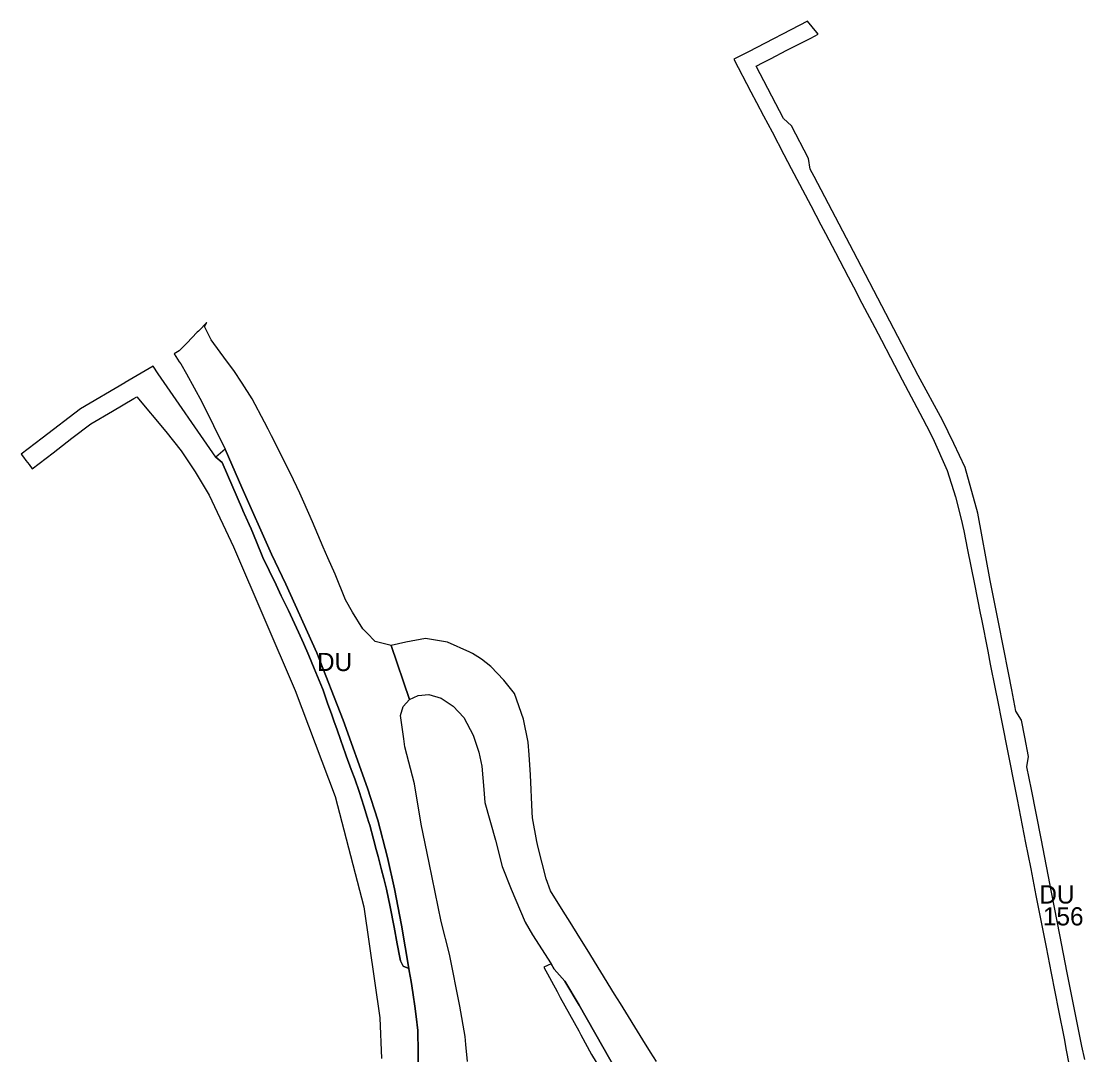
# Model space of a CAD drawing. Extents: x -521047 to -518054, y -1194945 to -1189555.
# Drawn here: x -520976 to -520392, y -1190123 to -1189555 of the extents above; entities that cross this region are included whole.
import ezdxf

# ---------------------------------------------------------------- set-up
doc = ezdxf.new("R2010")
doc.units = 0
for name, color, linetype in [('90310013', 7, 'Continuous'), ('90310023', 7, 'Continuous'), ('90320013', 7, 'Continuous'), ('ID_navrh', 7, 'Continuous')]:
    doc.layers.add(name, color=color, linetype=linetype)

msp = doc.modelspace()

# ---------------------------------------------------------------- linework, layer by layer
at = {"layer": '90310013'}
for points in [[(-520868.84, -1189794.27), (-520865.38, -1189797.27), (-520854.32, -1189823.02), (-520854.03, -1189823.64), (-520852.36, -1189827.29), (-520852.17, -1189827.72), (-520850.55, -1189831.25), (-520849.51, -1189833.76), (-520846.54, -1189840.93), (-520843.01, -1189849.46), (-520839.61, -1189856.58), (-520835.85, -1189864.43), (-520832.97, -1189870.44), (-520829.04, -1189878.62), (-520825.65, -1189885.69), (-520823.49, -1189890.54), (-520820.8, -1189896.58), (-520817.79, -1189903.36), (-520814.9, -1189910.36), (-520810.37, -1189921.35), (-520810.03, -1189922.31), (-520807.51, -1189929.41), (-520805.23, -1189935.82), (-520803.82, -1189939.77), (-520802.52, -1189943.48), (-520800.24, -1189949.98), (-520797.68, -1189957.29), (-520797.3, -1189958.38), (-520794.56, -1189965.83), (-520792.63, -1189971.08), (-520790.16, -1189978), (-520787.64, -1189985.97), (-520785.69, -1189992.16), (-520784.78, -1189995.03), (-520784.38, -1189996.52), (-520782.34, -1190004.2), (-520780.76, -1190009.83), (-520779.7, -1190013.73), (-520778.96, -1190016.65), (-520777.88, -1190020.97), (-520776.66, -1190025.8), (-520775.2, -1190031.58), (-520773.22, -1190041.38), (-520770.98, -1190052.51), (-520769.27, -1190061.72), (-520767.88, -1190069.17), (-520767.55, -1190070.93), (-520766.02, -1190074.02), (-520762.83, -1190075.3), (-520766.84, -1190051.34), (-520770.67, -1190031.38), (-520774.58, -1190014.33), (-520779.86, -1189993.71), (-520785.63, -1189976.16), (-520799.04, -1189938.79), (-520813.42, -1189901.77), (-520830.43, -1189864.05), (-520838.34, -1189847.6), (-520854.68, -1189811.01), (-520863.78, -1189789.93), (-520868.84, -1189794.27)], [(-520630.98, -1190162.68), (-520656.35, -1190118.25), (-520669.33, -1190095.42), (-520677.11, -1190082.08), (-520683.08, -1190075.53), (-520684.77, -1190072.63), (-520688.71, -1190074.44), (-520681.36, -1190087.92), (-520679.67, -1190091.18), (-520669.52, -1190109.47), (-520668.3, -1190111.67), (-520662.54, -1190122.49), (-520650.61, -1190142)]]:
    msp.add_lwpolyline(points, dxfattribs=at)
at = {"layer": '90310023'}
for points in [[(-520538.07, -1189562.04), (-520538.7, -1189561.06), (-520543.9, -1189554.92), (-520576.33, -1189571.62), (-520584.33, -1189575.74), (-520574.91, -1189593.69), (-520571.87, -1189599.49), (-520567.98, -1189606.88), (-520563.29, -1189615.69), (-520556.78, -1189628.12), (-520554.77, -1189631.94), (-520552.78, -1189635.77), (-520542.06, -1189656.2), (-520536.5, -1189666.75), (-520533.97, -1189671.56), (-520528.55, -1189681.89), (-520521.58, -1189695.28), (-520518.55, -1189700.78), (-520513.98, -1189709.68), (-520506.96, -1189723.04), (-520503.29, -1189730.03), (-520498.25, -1189739.55), (-520491.89, -1189751.79), (-520480.47, -1189773.36), (-520478.5, -1189777.12), (-520474.96, -1189783.97), (-520467.22, -1189801.74), (-520462.52, -1189816.05), (-520459.4, -1189828.36), (-520457.93, -1189834.89), (-520455.88, -1189845.31), (-520452.13, -1189864.14), (-520448.96, -1189880.06), (-520448.32, -1189883.37), (-520444.85, -1189900.94), (-520443.47, -1189908.13), (-520440.81, -1189921.53), (-520439.37, -1189928.74), (-520437.33, -1189939.01), (-520429.98, -1189976.03), (-520428.73, -1189982.35), (-520424.06, -1190006.15), (-520422.85, -1190012.32), (-520421.24, -1190020.5), (-520418.36, -1190035.16), (-520413.93, -1190058), (-520412.81, -1190063.42), (-520409.99, -1190077.75), (-520405.98, -1190098.21), (-520402.94, -1190113.68), (-520401.68, -1190120.11), (-520400.22, -1190127.57)], [(-520391.56, -1190125.16), (-520393.2, -1190117.89), (-520397.27, -1190097.65), (-520401.22, -1190077.65), (-520405.21, -1190056.77), (-520409.61, -1190034.24), (-520415.58, -1190003.82), (-520420.88, -1189976.82), (-520423.3, -1189964.53), (-520422.41, -1189958.68), (-520424.49, -1189948.09), (-520426.3, -1189938.88), (-520429.34, -1189933.8), (-520431.66, -1189922.07), (-520433.46, -1189912.89), (-520438.94, -1189885.01), (-520443.42, -1189862.15), (-520450.25, -1189825.06), (-520457.28, -1189799.95), (-520463.47, -1189786.79), (-520469.68, -1189773.95), (-520483.13, -1189749.49), (-520518.67, -1189681.41), (-520540.29, -1189640.25), (-520542.46, -1189636.12), (-520543.28, -1189630.26), (-520552.66, -1189612.4), (-520557.02, -1189608.4), (-520572.14, -1189579.59), (-520568.14, -1189577.53), (-520564.14, -1189575.47), (-520555.14, -1189570.83), (-520546.14, -1189566.2), (-520542.1, -1189564.12), (-520538.07, -1189562.04)], [(-520868.84, -1189794.27), (-520900.54, -1189748.5), (-520903.31, -1189744.33), (-520918.65, -1189753.34), (-520918.93, -1189753.5), (-520943.19, -1189767.73), (-520964.34, -1189783.94), (-520975.8, -1189792.72), (-520974.53, -1189794.42), (-520973.26, -1189796.11), (-520971.53, -1189798.42), (-520969.8, -1189800.72), (-520958.26, -1189791.88), (-520947.93, -1189783.96), (-520937.6, -1189776.04), (-520925.76, -1189769.09), (-520913.92, -1189762.15), (-520912.37, -1189761.25), (-520896.35, -1189780.16), (-520887.88, -1189790.95), (-520880.21, -1189802.32), (-520872.55, -1189815.19), (-520859.28, -1189843.65), (-520825.3, -1189922.44), (-520803.36, -1189980.65), (-520787.67, -1190041.34), (-520778.83, -1190102.4), (-520777.95, -1190124.57)], [(-520757.7, -1190126.98), (-520757.75, -1190120.86), (-520757.85, -1190109.85), (-520757.85, -1190109.21), (-520758.86, -1190101.6), (-520759.61, -1190095.86), (-520760.42, -1190089.68), (-520760.63, -1190088.46), (-520761.63, -1190082.43), (-520762.61, -1190076.58), (-520762.83, -1190075.3), (-520766.02, -1190074.02), (-520767.55, -1190070.93), (-520767.88, -1190069.17), (-520769.27, -1190061.72), (-520770.98, -1190052.51), (-520773.22, -1190041.38), (-520775.2, -1190031.58), (-520776.66, -1190025.8), (-520777.88, -1190020.97), (-520778.96, -1190016.65), (-520779.7, -1190013.73), (-520780.76, -1190009.83), (-520782.34, -1190004.2), (-520784.38, -1189996.52), (-520784.78, -1189995.03), (-520785.69, -1189992.16), (-520787.64, -1189985.97), (-520790.16, -1189978), (-520792.63, -1189971.08), (-520794.56, -1189965.83), (-520797.3, -1189958.38), (-520797.68, -1189957.29), (-520800.24, -1189949.98), (-520802.52, -1189943.48), (-520803.82, -1189939.77), (-520805.23, -1189935.82), (-520807.51, -1189929.41), (-520810.03, -1189922.31), (-520810.37, -1189921.35), (-520814.9, -1189910.36), (-520817.79, -1189903.36), (-520820.8, -1189896.58), (-520823.49, -1189890.54), (-520825.65, -1189885.69), (-520829.04, -1189878.62), (-520832.97, -1189870.44), (-520835.85, -1189864.43), (-520839.61, -1189856.58), (-520843.01, -1189849.46), (-520846.54, -1189840.93), (-520849.51, -1189833.76), (-520850.55, -1189831.25), (-520852.17, -1189827.72), (-520852.36, -1189827.29), (-520854.03, -1189823.64), (-520854.32, -1189823.02), (-520865.38, -1189797.27), (-520868.84, -1189794.27)]]:
    msp.add_lwpolyline(points, dxfattribs=at)
at = {"layer": '90320013'}
for points in [[(-520862.97, -1189741.45), (-520871.46, -1189729.85), (-520875.18, -1189722.65), (-520873.85, -1189720.38), (-520878.3, -1189724.93), (-520878.47, -1189725.11), (-520879.1, -1189725.76), (-520884.86, -1189731.67), (-520885.77, -1189732.6), (-520886.75, -1189733.61), (-520889.06, -1189735.97), (-520891.87, -1189737.62), (-520889, -1189741.91), (-520888.2, -1189743.1), (-520884.99, -1189748.66), (-520876.58, -1189763.88), (-520863.78, -1189789.93), (-520854.68, -1189811.01), (-520838.34, -1189847.6), (-520830.43, -1189864.05), (-520813.42, -1189901.77), (-520799.04, -1189938.79), (-520785.63, -1189976.16), (-520779.86, -1189993.71), (-520774.58, -1190014.33), (-520770.67, -1190031.38), (-520766.84, -1190051.34), (-520762.83, -1190075.3), (-520762.61, -1190076.58), (-520761.63, -1190082.43), (-520760.63, -1190088.46), (-520760.42, -1190089.68), (-520759.61, -1190095.86), (-520758.86, -1190101.6), (-520757.85, -1190109.21), (-520757.85, -1190109.85), (-520757.75, -1190120.86), (-520757.7, -1190126.98)], [(-520730.74, -1190126.36), (-520731.61, -1190116.98), (-520731.89, -1190112.51), (-520734.91, -1190095.84), (-520740.47, -1190067.29), (-520745.18, -1190049.33), (-520751.63, -1190017.23), (-520756.09, -1189995.85), (-520759.8, -1189973.83), (-520765.09, -1189953.48), (-520765.67, -1189949.12), (-520767.38, -1189936.19), (-520766.03, -1189931.34), (-520762.53, -1189927.5), (-520772.63, -1189897.76), (-520781.3, -1189895.57), (-520785.91, -1189890.86), (-520788.07, -1189888.65), (-520793.8, -1189879.57), (-520797.65, -1189872.73), (-520803.4, -1189858.68), (-520807.32, -1189849.61), (-520809.87, -1189843.72), (-520815.85, -1189829.79), (-520820.55, -1189819.14), (-520822.82, -1189814.19), (-520827.89, -1189803.41), (-520838.28, -1189782.7), (-520840.25, -1189778.89), (-520842.22, -1189775.08), (-520848.98, -1189762.26), (-520854.49, -1189753.78), (-520859.09, -1189746.74), (-520862.97, -1189741.45)], [(-520626.81, -1190126.38), (-520630.08, -1190121.08), (-520634.26, -1190114.38), (-520646.54, -1190094.49), (-520649.81, -1190089.25), (-520664.99, -1190064.75), (-520668.96, -1190058.36), (-520674.3, -1190049.78), (-520678.04, -1190043.73), (-520685.06, -1190032.49), (-520687.51, -1190025.96), (-520691.84, -1190008.79), (-520692.55, -1190005.5), (-520694.98, -1189992.45), (-520695.16, -1189989.28), (-520696, -1189968.88), (-520696.76, -1189957.88), (-520697.31, -1189950.87), (-520699.84, -1189938.24), (-520704.82, -1189924.14), (-520710.73, -1189916.79), (-520717.89, -1189909.3), (-520722.93, -1189905.34), (-520724.92, -1189904.07), (-520727.89, -1189902.2), (-520729.38, -1189901.54), (-520741.72, -1189895.94), (-520753.69, -1189893.86), (-520764.56, -1189895.88), (-520772.63, -1189897.76), (-520762.53, -1189927.5), (-520757.73, -1189925.33), (-520751.84, -1189924.64), (-520745.07, -1189926.77), (-520738.61, -1189931.05), (-520732.65, -1189937.29), (-520727.49, -1189947.13), (-520724.42, -1189956.39), (-520722.75, -1189964.15), (-520721.7, -1189976.9), (-520721.1, -1189984.1), (-520715.35, -1190004.73), (-520711.57, -1190019.13), (-520706.59, -1190031.62), (-520698.97, -1190049.7), (-520695.03, -1190056.68), (-520684.77, -1190072.63), (-520683.08, -1190075.53), (-520677.11, -1190082.08), (-520669.33, -1190095.42), (-520656.35, -1190118.25), (-520630.98, -1190162.68)]]:
    msp.add_lwpolyline(points, dxfattribs=at)

# ---------------------------------------------------------------- texts
at = {"layer": '90310013'}
msp.add_text('DU', height=10, rotation=0, dxfattribs=at).set_placement((-520813.32, -1189911.83))
at = {"layer": '90310023'}
msp.add_text('DU', height=10, rotation=0, dxfattribs=at).set_placement((-520416.49, -1190039.54))
at = {"layer": 'ID_navrh'}
msp.add_text('156', height=10, rotation=360, dxfattribs=at).set_placement((-520414.53, -1190051.57))

doc.saveas('drawing.dxf')
